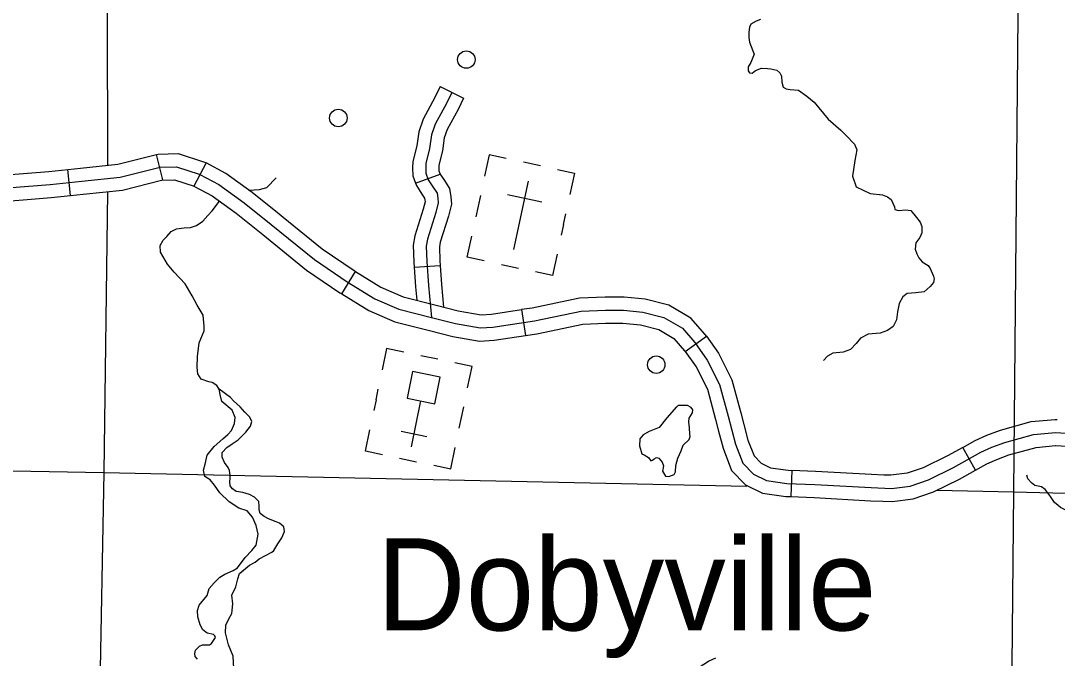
# Model space of a CAD drawing. Extents: x 1369979 to 1371646, y 379997 to 381064.
# Drawn here: x 1370664.4 to 1370734.1, y 380287.1 to 380329.9 of the extents above; entities that cross this region are included whole.
import ezdxf

# ---------------------------------------------------------------- set-up
doc = ezdxf.new("R2010")
doc.units = 0
doc.layers.add('R_Border Notes', color=7, linetype='Continuous')

msp = doc.modelspace()

# ---------------------------------------------------------------- linework, layer by layer
at = {"layer": 'R_Border Notes'}
for p, q in [((1370692.607, 380325.488), (1370694.191, 380324.725)), ((1370673.992, 380319.221), (1370673.561, 380320.926)), ((1370667.787, 380318.175), (1370667.595, 380319.922)), ((1370676.888, 380320.364), (1370676.065, 380318.811)), ((1370699.353, 380320.16), (1370698.207, 380320.406)), ((1370690.964, 380318.999), (1370692.616, 380319.599)), ((1370698.528, 380319.138), (1370697.545, 380314.555)), ((1370695.324, 380318.167), (1370695.017, 380316.735)), ((1370697.137, 380318.238), (1370699.439, 380317.745)), ((1370682.07, 380316.708), (1370682.07, 380316.708)), ((1370698.037, 380316.847), (1370698.037, 380316.847)), ((1370698.037, 380316.847), (1370698.037, 380316.847)), ((1370700.901, 380316.232), (1370701.053, 380316.938)), ((1370700.901, 380316.232), (1370700.746, 380315.506)), ((1370686.003, 380311.569), (1370686.92, 380313.068)), ((1370690.865, 380313.352), (1370692.619, 380313.479)), ((1370696.733, 380313.531), (1370697.879, 380313.285)), ((1370698.085, 380310.51), (1370698.345, 380308.772)), ((1370709.063, 380307.7), (1370710.496, 380308.718)), ((1370692.455, 380307.179), (1370691.307, 380307.416)), ((1370688.306, 380304.448), (1370688.456, 380305.175)), ((1370688.306, 380304.448), (1370688.159, 380303.741)), ((1370690.68, 380301.293), (1370691.32, 380304.383)), ((1370693.897, 380302.553), (1370694.194, 380303.987)), ((1370691.719, 380301.976), (1370689.998, 380302.332)), ((1370728.574, 380299.722), (1370727.726, 380301.261)), ((1370689.881, 380300.531), (1370691.029, 380300.294)), ((1370716.242, 380299.709), (1370716.169, 380297.952)), ((1370722.418, 380299.403), (1370722.418, 380299.403))]:
    msp.add_line(p, q, dxfattribs=at)
for points in [[(1370670.192, 380361.014), (1370670.269, 380320.2)], [(1370731.684, 380359.882), (1370731.13, 380298.274)], [(1370714.142, 380329.993), (1370713.831, 380329.89), (1370713.491, 380329.682), (1370713.387, 380329.475), (1370713.343, 380329.149), (1370713.343, 380328.794), (1370713.402, 380328.468), (1370713.609, 380327.89), (1370713.698, 380327.668), (1370713.476, 380327.12), (1370713.298, 380326.809), (1370713.298, 380326.542), (1370713.387, 380326.409), (1370713.58, 380326.394), (1370713.787, 380326.571), (1370714.201, 380326.72), (1370714.601, 380326.705), (1370714.823, 380326.694), (1370715.237, 380326.601), (1370715.43, 380326.409), (1370715.548, 380326.201), (1370715.563, 380325.786), (1370715.652, 380325.46), (1370715.844, 380325.342), (1370716.125, 380325.298), (1370716.688, 380325.258)], [(1370692.607, 380325.488), (1370692.252, 380324.751), (1370691.474, 380323.314), (1370691.175, 380322.463), (1370691.038, 380321.509), (1370690.781, 380320.459), (1370690.763, 380320.024), (1370690.782, 380319.5), (1370690.964, 380318.999)], [(1370693.399, 380325.106), (1370693.035, 380324.351), (1370692.28, 380322.957), (1370692.033, 380322.253), (1370691.902, 380321.342), (1370691.655, 380320.334), (1370691.642, 380320.022), (1370691.655, 380319.67), (1370691.811, 380319.24), (1370692.124, 380318.758), (1370692.41, 380318.328), (1370692.462, 380317.99), (1370692.488, 380317.677), (1370692.319, 380317.026), (1370691.759, 380315.254), (1370691.68, 380314.78), (1370691.719, 380313.737), (1370691.836, 380312.122), (1370692.031, 380309.985)], [(1370694.191, 380324.725), (1370693.817, 380323.95), (1370693.086, 380322.6), (1370692.89, 380322.044), (1370692.766, 380321.174), (1370692.53, 380320.21), (1370692.522, 380320.02), (1370692.528, 380319.84), (1370692.616, 380319.599)], [(1370716.688, 380325.258), (1370717.25, 380324.858), (1370717.738, 380324.443), (1370718.686, 380323.302), (1370719.529, 380322.576)], [(1370719.529, 380322.576), (1370719.87, 380322.225), (1370720.447, 380321.618), (1370720.595, 380321.247), (1370720.462, 380320.536), (1370720.314, 380319.47), (1370720.565, 380318.759), (1370721.498, 380318.316)], [(1370667.595, 380319.922), (1370668.454, 380320.016), (1370670.97, 380320.271), (1370673.561, 380320.926)], [(1370673.561, 380320.926), (1370673.684, 380320.957), (1370675.024, 380320.988), (1370676.775, 380320.424), (1370676.888, 380320.364)], [(1370697.055, 380320.653), (1370695.91, 380320.899), (1370695.602, 380319.466)], [(1370661.471, 380319.411), (1370662.031, 380319.446), (1370666.33, 380319.783), (1370667.595, 380319.922)], [(1370662.092, 380318.569), (1370666.412, 380318.908), (1370668.546, 380319.142), (1370671.123, 380319.403), (1370673.803, 380320.08), (1370674.897, 380320.106), (1370676.432, 380319.611), (1370676.476, 380319.588)], [(1370682.07, 380316.708), (1370681.809, 380316.921), (1370679.984, 380318.383), (1370678.225, 380319.656), (1370676.888, 380320.364)], [(1370700.493, 380319.916), (1370701.639, 380319.67), (1370701.331, 380318.238)], [(1370667.787, 380318.175), (1370668.639, 380318.268), (1370671.276, 380318.535), (1370673.992, 380319.221)], [(1370673.923, 380319.204), (1370674.769, 380319.224), (1370676.089, 380318.799), (1370676.065, 380318.811)], [(1370676.476, 380319.588), (1370677.759, 380318.908), (1370679.451, 380317.684), (1370681.257, 380316.237)], [(1370679.77, 380318.538), (1370680.489, 380318.578), (1370680.962, 380318.711), (1370681.594, 380319.362)], [(1370692.603, 380319.634), (1370692.858, 380319.241), (1370693.249, 380318.654), (1370693.335, 380318.093), (1370693.376, 380317.601), (1370693.164, 380316.783), (1370692.616, 380315.048), (1370692.561, 380314.723), (1370692.596, 380313.786), (1370692.619, 380313.479)], [(1370676.065, 380318.811), (1370677.294, 380318.16), (1370678.918, 380316.984), (1370680.705, 380315.553), (1370680.961, 380315.345)], [(1370690.964, 380318.999), (1370691.019, 380318.846), (1370691.389, 380318.276), (1370691.571, 380318.003), (1370691.589, 380317.886), (1370691.6, 380317.753), (1370691.474, 380317.269), (1370690.903, 380315.46), (1370690.798, 380314.836), (1370690.841, 380313.689), (1370690.865, 380313.352)], [(1370661.58, 380317.657), (1370662.154, 380317.693), (1370666.495, 380318.033), (1370667.787, 380318.175)], [(1370670.272, 380318.434), (1370670.024, 380299.56)], [(1370673.822, 380314.38), (1370673.807, 380314.82), (1370674.014, 380315.175), (1370674.251, 380315.426), (1370674.546, 380315.752), (1370674.901, 380315.929), (1370675.419, 380316.003), (1370675.847, 380316.018), (1370676.246, 380316.166), (1370676.675, 380316.462), (1370677, 380316.832), (1370677.311, 380317.157), (1370677.789, 380317.801)], [(1370721.498, 380318.316), (1370722.326, 380318.211), (1370722.652, 380318.092), (1370722.904, 380317.914), (1370723.137, 380317.413)], [(1370723.137, 380317.413), (1370723.155, 380317.233), (1370723.407, 380317.159), (1370723.866, 380317.218), (1370724.221, 380317.174), (1370724.62, 380316.7)], [(1370686.92, 380313.068), (1370686.834, 380313.121), (1370684.697, 380314.572), (1370682.07, 380316.708)], [(1370724.62, 380316.7), (1370724.854, 380316.383), (1370724.973, 380316.086), (1370724.973, 380315.672), (1370724.839, 380315.346), (1370724.558, 380314.99), (1370724.514, 380314.575), (1370724.632, 380314.25), (1370724.765, 380313.983), (1370724.987, 380313.731), (1370725.402, 380313.464), (1370725.52, 380313.272)], [(1370681.257, 380316.237), (1370684.171, 380313.867), (1370686.358, 380312.382), (1370688.231, 380311.235), (1370689.845, 380310.532), (1370692.031, 380309.985), (1370693.645, 380309.568), (1370695.31, 380309.282), (1370696.161, 380309.334), (1370698.946, 380309.751), (1370702.095, 380310.402), (1370703.709, 380310.48), (1370704.932, 380310.48), (1370706.233, 380310.35), (1370707.638, 380309.985), (1370708.888, 380309.256), (1370709.72, 380308.292), (1370710.553, 380307.119), (1370711.386, 380305.486)], [(1370680.961, 380315.345), (1370683.646, 380313.161), (1370685.881, 380311.643), (1370686.003, 380311.569)], [(1370695.581, 380313.778), (1370694.435, 380314.024), (1370694.742, 380315.456)], [(1370676.687, 380310.14), (1370676.291, 380310.8), (1370675.951, 380311.436), (1370675.493, 380312.25), (1370674.753, 380313.019), (1370674.295, 380313.566), (1370673.822, 380314.38)], [(1370700.471, 380314.227), (1370700.164, 380312.795), (1370699.018, 380313.041)], [(1370686.92, 380313.068), (1370688.638, 380312.017), (1370690.129, 380311.367), (1370692.248, 380310.837), (1370692.346, 380310.811)], [(1370690.865, 380313.352), (1370690.96, 380312.05), (1370691.043, 380311.138)], [(1370692.619, 380313.479), (1370692.712, 380312.194), (1370692.85, 380310.681)], [(1370725.52, 380313.272), (1370725.757, 380312.768), (1370725.801, 380312.59), (1370725.757, 380312.339), (1370725.52, 380312.057), (1370725.135, 380311.702), (1370724.558, 380311.642), (1370723.981, 380311.598), (1370723.685, 380311.376), (1370723.448, 380310.916), (1370723.33, 380310.354)], [(1370686.003, 380311.569), (1370687.825, 380310.454), (1370689.561, 380309.697), (1370691.814, 380309.133), (1370691.907, 380309.109)], [(1370692.346, 380310.811), (1370693.829, 380310.428), (1370695.359, 380310.165), (1370696.069, 380310.209), (1370698.085, 380310.51)], [(1370704.326, 380311.359), (1370703.687, 380311.359), (1370701.984, 380311.276), (1370698.792, 380310.616), (1370698.085, 380310.51)], [(1370710.496, 380308.718), (1370710.413, 380308.835), (1370709.457, 380309.941), (1370707.977, 380310.805), (1370706.388, 380311.218), (1370704.976, 380311.359), (1370704.326, 380311.359)], [(1370677.958, 380304.337), (1370677.84, 380304.814), (1370677.781, 380305.169), (1370677.603, 380305.405), (1370677.293, 380305.613), (1370677.071, 380305.657), (1370676.554, 380305.849), (1370676.332, 380306.204), (1370676.288, 380306.619), (1370676.317, 380307.373), (1370676.436, 380308.276), (1370676.761, 380309.089), (1370676.761, 380309.4), (1370676.687, 380310.14)], [(1370723.33, 380310.354), (1370723.256, 380309.828), (1370723.034, 380309.368), (1370722.664, 380309.102), (1370722.161, 380308.924), (1370721.361, 380308.865), (1370720.858, 380308.583), (1370720.547, 380308.228), (1370720.177, 380307.843), (1370719.689, 380307.65), (1370718.993, 380307.591), (1370718.638, 380307.383), (1370718.372, 380307.087)], [(1370698.345, 380308.772), (1370699.1, 380308.885), (1370702.206, 380309.527), (1370703.73, 380309.601), (1370704.326, 380309.601)], [(1370704.326, 380309.601), (1370704.888, 380309.601), (1370706.078, 380309.482), (1370707.3, 380309.165), (1370708.318, 380308.57), (1370709.028, 380307.749), (1370709.063, 380307.7)], [(1370691.907, 380309.109), (1370693.46, 380308.708), (1370695.262, 380308.398), (1370696.253, 380308.459), (1370698.345, 380308.772)], [(1370710.496, 380308.718), (1370711.307, 380307.576), (1370712.211, 380305.803), (1370712.808, 380303.576), (1370713.014, 380302.794)], [(1370690.166, 380307.653), (1370689.018, 380307.89), (1370688.721, 380306.456)], [(1370709.063, 380307.7), (1370709.799, 380306.663), (1370710.561, 380305.169), (1370711.109, 380303.124), (1370711.314, 380302.346)], [(1370694.459, 380305.268), (1370694.756, 380306.702), (1370693.609, 380306.94)], [(1370711.386, 380305.486), (1370711.958, 380303.35), (1370712.453, 380301.474), (1370712.947, 380300.198), (1370713.65, 380299.468), (1370714.535, 380299.025), (1370715.906, 380298.843), (1370717.78, 380298.765), (1370721.554, 380298.557), (1370722.933, 380298.504), (1370724.182, 380298.661), (1370725.406, 380299.078), (1370727.097, 380299.911), (1370728.94, 380300.927)], [(1370678.535, 380304.614), (1370677.781, 380305.169)], [(1370679.052, 380301.763), (1370679.555, 380302.276), (1370679.88, 380302.69), (1370679.968, 380303.001), (1370679.835, 380303.297), (1370679.495, 380303.622), (1370679.185, 380303.992), (1370678.742, 380304.392), (1370678.535, 380304.614)], [(1370678.446, 380297.598), (1370677.81, 380298.212), (1370677.456, 380298.73), (1370677.16, 380299.07), (1370676.805, 380299.307), (1370676.716, 380299.736), (1370676.82, 380300.135), (1370676.968, 380300.727), (1370677.426, 380301.319), (1370678.017, 380301.822), (1370678.357, 380302.118), (1370678.594, 380302.384), (1370678.801, 380302.872), (1370678.845, 380303.257), (1370678.653, 380303.76), (1370677.958, 380304.337)], [(1370708.485, 380303.976), (1370707.849, 380303.25), (1370707.316, 380302.599), (1370706.65, 380302.317), (1370706.251, 380302.11), (1370706.029, 380301.828), (1370706.014, 380301.354), (1370706.162, 380300.836), (1370706.325, 380300.762), (1370706.606, 380300.569), (1370706.769, 380300.362), (1370706.872, 380300.391), (1370706.991, 380300.48), (1370707.153, 380300.569), (1370707.301, 380300.539), (1370707.523, 380300.273), (1370707.627, 380300.021), (1370707.553, 380299.651), (1370707.745, 380299.325), (1370707.967, 380299.295), (1370708.323, 380299.428), (1370708.411, 380299.621), (1370708.441, 380300.036), (1370708.589, 380300.539), (1370708.796, 380301.028), (1370708.944, 380301.413), (1370709.329, 380301.784), (1370709.403, 380301.991), (1370709.388, 380302.139), (1370709.359, 380302.569), (1370709.314, 380302.969), (1370709.329, 380303.221), (1370709.566, 380303.576), (1370709.595, 380303.784), (1370709.477, 380303.947), (1370709.225, 380304.065), (1370708.944, 380304.065), (1370708.604, 380304.065), (1370708.515, 380303.991)], [(1370727.725, 380301.261), (1370728.542, 380301.711), (1370729.33, 380302.078), (1370730.262, 380302.422), (1370732.321, 380302.994), (1370733.923, 380303.137), (1370734.065, 380303.129)], [(1370688.74, 380300.768), (1370687.593, 380301.005), (1370687.89, 380302.44)], [(1370713.014, 380302.794), (1370713.29, 380301.746), (1370713.703, 380300.68), (1370714.178, 380300.187), (1370714.797, 380299.877), (1370715.983, 380299.72), (1370716.242, 380299.709)], [(1370679.362, 380298.219), (1370678.904, 380298.286), (1370678.668, 380298.463), (1370678.505, 380298.685), (1370678.49, 380298.966), (1370678.52, 380299.159), (1370678.52, 380299.395), (1370678.475, 380299.706), (1370678.372, 380299.913), (1370678.136, 380300.239), (1370677.973, 380300.594), (1370677.973, 380300.905), (1370678.283, 380301.245), (1370678.638, 380301.496), (1370679.052, 380301.763)], [(1370711.314, 380302.346), (1370711.616, 380301.203), (1370712.192, 380299.715), (1370713.122, 380298.75), (1370714.273, 380298.174), (1370715.83, 380297.967), (1370716.169, 380297.952)], [(1370728.94, 380300.927), (1370729.669, 380301.266), (1370730.532, 380301.585), (1370732.479, 380302.125), (1370733.937, 380302.256), (1370735.732, 380302.152)], [(1370733.963, 380301.374), (1370735.715, 380301.272), (1370737.276, 380301.299), (1370738.243, 380301.358), (1370739.047, 380301.574), (1370739.981, 380301.925), (1370740.48, 380302.204)], [(1370692.183, 380300.055), (1370693.33, 380299.817), (1370693.627, 380301.252)], [(1370727.726, 380301.261), (1370726.691, 380300.691), (1370725.068, 380299.891), (1370723.984, 380299.522), (1370722.895, 380299.385), (1370722.418, 380299.403)], [(1370728.574, 380299.722), (1370729.338, 380300.143), (1370730.007, 380300.454), (1370730.802, 380300.748), (1370732.637, 380301.257), (1370733.95, 380301.375), (1370733.963, 380301.374)], [(1370607.61, 380300.722), (1370670.024, 380299.56)], [(1370722.418, 380299.403), (1370721.595, 380299.435), (1370717.823, 380299.643), (1370716.242, 380299.709)], [(1370722.352, 380297.647), (1370722.971, 380297.623), (1370724.381, 380297.8), (1370725.743, 380298.264), (1370727.504, 380299.132), (1370728.574, 380299.722)], [(1370670.024, 380299.56), (1370668.871, 380237.248)], [(1370670.024, 380299.56), (1370713.217, 380298.651)], [(1370735.558, 380294.805), (1370735.635, 380295.419), (1370735.605, 380295.907), (1370735.576, 380296.262), (1370735.428, 380296.543), (1370735.25, 380296.736), (1370734.955, 380296.898), (1370734.63, 380297.031), (1370734.29, 380297.224), (1370734.127, 380297.357), (1370733.876, 380297.549), (1370733.654, 380297.89), (1370733.506, 380298.126), (1370733.255, 380298.437), (1370733.004, 380298.6), (1370732.56, 380298.703), (1370732.324, 380298.881), (1370732.087, 380299.147), (1370732.013, 380299.384)], [(1370725.984, 380298.383), (1370731.13, 380298.274)], [(1370731.13, 380298.274), (1370730.521, 380235.229)], [(1370731.13, 380298.274), (1370792.932, 380296.7)], [(1370679.011, 380293.165), (1370679.51, 380293.869), (1370679.954, 380294.328), (1370680.264, 380294.683), (1370680.397, 380295.423), (1370680.264, 380296), (1370680.013, 380296.562), (1370679.658, 380296.991), (1370679.096, 380297.183), (1370678.446, 380297.598)], [(1370681.594, 380296.251), (1370681.077, 380296.459), (1370680.796, 380296.606), (1370680.515, 380296.828), (1370680.456, 380297.065), (1370680.456, 380297.302), (1370680.427, 380297.627), (1370680.146, 380297.923), (1370679.806, 380298.086), (1370679.362, 380298.219)], [(1370716.169, 380297.952), (1370717.738, 380297.887), (1370721.513, 380297.679), (1370722.352, 380297.647)], [(1370679.144, 380292.795), (1370679.806, 380293.352), (1370680.19, 380293.544), (1370680.456, 380293.766), (1370681.299, 380294.21), (1370681.432, 380294.328), (1370681.713, 380294.772), (1370681.979, 380295.186), (1370682.156, 380295.6), (1370682.112, 380295.911), (1370681.816, 380296.177), (1370681.594, 380296.251)], [(1370676.32, 380287.035), (1370676.158, 380287.217), (1370676.143, 380287.41), (1370676.173, 380287.632), (1370676.439, 380287.898), (1370676.646, 380288.002), (1370676.926, 380288.002), (1370677.119, 380288.002), (1370677.266, 380288.09), (1370677.34, 380288.223), (1370677.532, 380288.49), (1370677.488, 380288.593), (1370677.385, 380288.697), (1370676.971, 380288.786), (1370676.675, 380288.993), (1370676.498, 380289.348), (1370676.335, 380289.866), (1370676.32, 380290.31), (1370676.424, 380290.665), (1370676.956, 380291.301), (1370677.104, 380291.774), (1370677.429, 380292.159), (1370677.813, 380292.544), (1370678.153, 380292.751), (1370678.715, 380292.987), (1370679.011, 380293.165)], [(1370678.626, 380291.335), (1370678.892, 380291.893), (1370679.025, 380292.44), (1370679.144, 380292.795), (1370679.336, 380292.973)], [(1370678.759, 380286.414), (1370678.715, 380287.237), (1370678.39, 380287.991), (1370678.198, 380288.805), (1370678.212, 380289.323), (1370678.419, 380289.737), (1370678.612, 380290.107), (1370678.685, 380290.758), (1370678.626, 380291.335)], [(1370707.789, 380284.943), (1370708.484, 380285.617), (1370709.045, 380285.853), (1370709.592, 380286.149), (1370710.021, 380286.489), (1370710.642, 380286.889), (1370711.127, 380287.116)]]:
    msp.add_lwpolyline(points, dxfattribs=at)
msp.add_lwpolyline([(1370690.766, 380306.365), (1370690.395, 380304.575), (1370692.252, 380304.19), (1370692.623, 380305.981)], close=True, dxfattribs=at)
for centre in [(1370694.375, 380327.306), (1370685.775, 380323.382), (1370707.129, 380306.812)]:
    msp.add_circle(centre, 0.586, dxfattribs=at)

# ---------------------------------------------------------------- texts
msp.add_text('Dobyville', height=6.1875, dxfattribs=at).set_placement((1370688.353, 380288.968))

doc.saveas('drawing.dxf')
